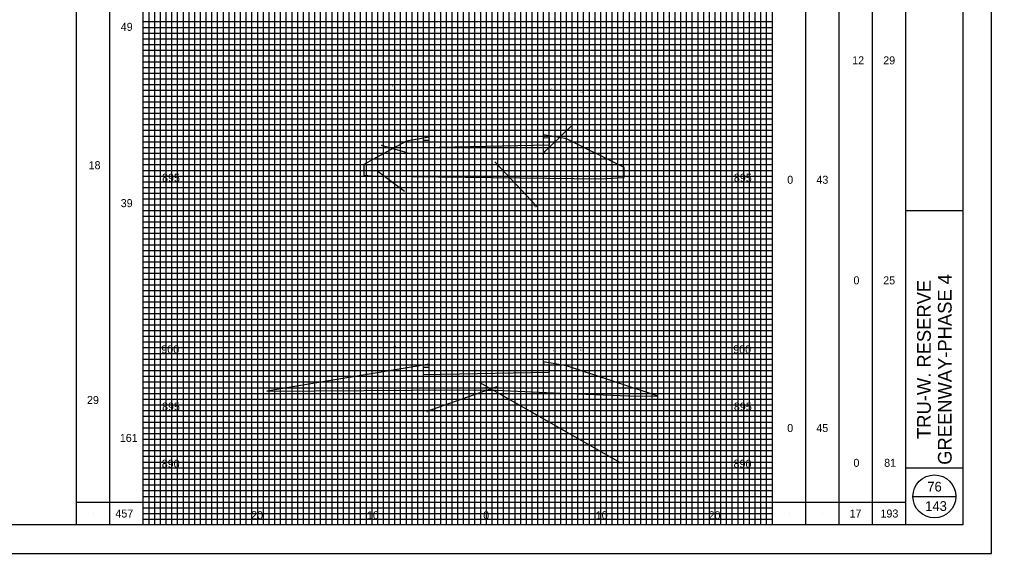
# Model space of a CAD drawing. Extents: x -73 to 160, y -2 to 1877.
# Drawn here: x 75 to 160, y 227.5 to 274.2 of the extents above; entities that cross this region are included whole.
import ezdxf

# ---------------------------------------------------------------- set-up
doc = ezdxf.new("R2010")
doc.units = 0
for name, color, linetype in [('DR_P_Flood_Boundary', 7, 'Continuous'), ('GK_Cells', 7, 'Continuous'), ('RD_X_Fence', 7, 'Continuous'), ('TX_X_5', 7, 'Continuous'), ('UT_P_Water_Cells', 7, 'Continuous'), ('XS_P_Pavt_Layers', 7, 'Continuous'), ('XS_P_Pavt_Surface', 7, 'Continuous'), ('XS_X_Ground_Line', 7, 'Continuous')]:
    doc.layers.add(name, color=color, linetype=linetype)

msp = doc.modelspace()

# ---------------------------------------------------------------- linework, layer by layer
at = {"layer": 'DR_P_Flood_Boundary'}
for p, q in [((90.832, 230), (90.832, 335)), ((95.832, 230), (95.832, 335)), ((100.832, 230), (100.832, 335)), ((105.832, 230), (105.832, 335)), ((110.832, 230), (110.832, 335)), ((115.832, 230), (115.832, 335)), ((120.832, 230), (120.832, 335)), ((125.832, 230), (125.832, 335)), ((130.832, 230), (130.832, 335)), ((135.832, 230), (135.832, 335)), ((85.832, 270), (140.832, 270)), ((85.832, 265), (140.832, 265)), ((85.832, 260), (140.832, 260)), ((85.832, 255), (140.832, 255)), ((85.832, 250), (140.832, 250)), ((85.832, 245), (140.832, 245)), ((85.832, 240), (140.832, 240)), ((85.832, 235), (140.832, 235))]:
    msp.add_line(p, q, dxfattribs=at)
at = {"layer": 'GK_Cells'}
for p, q in [((152.5, 230), (152.5, 335)), ((152.5, 257.5), (157.5, 257.5)), ((152.5, 235), (157.5, 235))]:
    msp.add_line(p, q, dxfattribs=at)
msp.add_lwpolyline([(0, 335), (157.5, 335), (157.5, 230), (0, 230)], close=True, dxfattribs=at)
at = {"layer": 'RD_X_Fence'}
for p, q in [((120.719, 262.403), (123.237, 264.87)), ((110.832, 263.9), (108.832, 263.567)), ((110.332, 263.64), (110.832, 263.65)), ((110.332, 262.973), (110.332, 263.64)), ((120.832, 263.85), (121.332, 263.86)), ((121.332, 263.86), (121.332, 263.193)), ((127.866, 261.25), (122.832, 263.767)), ((108.901, 262.546), (106.646, 263.188)), ((121.332, 263.193), (110.332, 262.973)), ((105.123, 261.511), (105.123, 260.571)), ((116.57, 261.744), (120.23, 257.835)), ((127.866, 260.374), (127.866, 261.25)), ((105.123, 260.571), (105.832, 260.51)), ((106.334, 260.939), (108.682, 259.172)), ((125.832, 260.25), (127.866, 260.374)), ((110.832, 244.05), (96.645, 241.685)), ((122.832, 243.917), (120.832, 244.25)), ((120.832, 244), (121.332, 244.01)), ((121.332, 244.01), (121.332, 243.343)), ((110.332, 243.79), (110.832, 243.8)), ((110.332, 243.123), (110.332, 243.79)), ((121.332, 243.343), (110.332, 243.123)), ((130.84, 241.247), (122.832, 243.917)), ((115.258, 242.457), (127.523, 235.468)), ((96.645, 241.685), (109.332, 241.79)), ((109.332, 241.79), (112.308, 241.814)), ((116.749, 242.071), (110.613, 239.914)), ((112.308, 241.814), (115.833, 241.782)), ((116.697, 241.774), (120.445, 241.609)), ((120.445, 241.609), (122.332, 241.53))]:
    msp.add_line(p, q, dxfattribs=at)
for points in [[(108.832, 263.567), (107.639, 262.905), (105.123, 261.511)], [(110.832, 263.65), (110.832, 263.796), (110.832, 263.9)], [(122.832, 263.767), (122.216, 263.869), (120.832, 264.1)], [(120.832, 264.1), (120.832, 263.996), (120.832, 263.85)], [(105.832, 260.51), (106.923, 260.496), (125.832, 260.25)], [(110.832, 243.8), (110.832, 243.946), (110.832, 244.05)], [(120.832, 244.25), (120.832, 244.146), (120.832, 244)], [(115.833, 241.782), (115.924, 241.781), (116.697, 241.774)], [(122.332, 241.53), (128.241, 241.281), (130.84, 241.247)]]:
    msp.add_lwpolyline(points, dxfattribs=at)
at = {"layer": 'TX_X_5'}
msp.add_lwpolyline([(-10, 227.5), (160, 227.5), (160, 337.5), (-10, 337.5)], close=True, dxfattribs=at)
at = {"layer": 'UT_P_Water_Cells'}
for p, q in [((86.332, 230), (86.332, 335)), ((86.832, 230), (86.832, 335)), ((87.332, 230), (87.332, 335)), ((87.832, 230), (87.832, 335)), ((88.332, 230), (88.332, 335)), ((88.832, 230), (88.832, 335)), ((89.332, 230), (89.332, 335)), ((89.832, 230), (89.832, 335)), ((90.332, 230), (90.332, 335)), ((91.332, 230), (91.332, 335)), ((91.832, 230), (91.832, 335)), ((92.332, 230), (92.332, 335)), ((92.832, 230), (92.832, 335)), ((93.332, 230), (93.332, 335)), ((93.832, 230), (93.832, 335)), ((94.332, 230), (94.332, 335)), ((94.832, 230), (94.832, 335)), ((95.332, 230), (95.332, 335)), ((96.332, 230), (96.332, 335)), ((96.832, 230), (96.832, 335)), ((97.332, 230), (97.332, 335)), ((97.832, 230), (97.832, 335)), ((98.332, 230), (98.332, 335)), ((98.832, 230), (98.832, 335)), ((99.332, 230), (99.332, 335)), ((99.832, 230), (99.832, 335)), ((100.332, 230), (100.332, 335)), ((101.332, 230), (101.332, 335)), ((101.832, 230), (101.832, 335)), ((102.332, 230), (102.332, 335)), ((102.832, 230), (102.832, 335)), ((103.332, 230), (103.332, 335)), ((103.832, 230), (103.832, 335)), ((104.332, 230), (104.332, 335)), ((104.832, 230), (104.832, 335)), ((105.332, 230), (105.332, 335)), ((106.332, 230), (106.332, 335)), ((106.832, 230), (106.832, 335)), ((107.332, 230), (107.332, 335)), ((107.832, 230), (107.832, 335)), ((108.332, 230), (108.332, 335)), ((108.832, 230), (108.832, 335)), ((109.332, 230), (109.332, 335)), ((109.832, 230), (109.832, 335)), ((110.332, 230), (110.332, 335)), ((111.332, 230), (111.332, 335)), ((111.832, 230), (111.832, 335)), ((112.332, 230), (112.332, 335)), ((112.832, 230), (112.832, 335)), ((113.332, 230), (113.332, 335)), ((113.832, 230), (113.832, 335)), ((114.332, 230), (114.332, 335)), ((114.832, 230), (114.832, 335)), ((115.332, 230), (115.332, 335)), ((116.332, 230), (116.332, 335)), ((116.832, 230), (116.832, 335)), ((117.332, 230), (117.332, 335)), ((117.832, 230), (117.832, 335)), ((118.332, 230), (118.332, 335)), ((118.832, 230), (118.832, 335)), ((119.332, 230), (119.332, 335)), ((119.832, 230), (119.832, 335)), ((120.332, 230), (120.332, 335)), ((121.332, 230), (121.332, 335)), ((121.832, 230), (121.832, 335)), ((122.332, 230), (122.332, 335)), ((122.832, 230), (122.832, 335)), ((123.332, 230), (123.332, 335)), ((123.832, 230), (123.832, 335)), ((124.332, 230), (124.332, 335)), ((124.832, 230), (124.832, 335)), ((125.332, 230), (125.332, 335)), ((126.332, 230), (126.332, 335)), ((126.832, 230), (126.832, 335)), ((127.332, 230), (127.332, 335)), ((127.832, 230), (127.832, 335)), ((128.332, 230), (128.332, 335)), ((128.832, 230), (128.832, 335)), ((129.332, 230), (129.332, 335)), ((129.832, 230), (129.832, 335)), ((130.332, 230), (130.332, 335)), ((131.332, 230), (131.332, 335)), ((131.832, 230), (131.832, 335)), ((132.332, 230), (132.332, 335)), ((132.832, 230), (132.832, 335)), ((133.332, 230), (133.332, 335)), ((133.832, 230), (133.832, 335)), ((134.332, 230), (134.332, 335)), ((134.832, 230), (134.832, 335)), ((135.332, 230), (135.332, 335)), ((136.332, 230), (136.332, 335)), ((136.832, 230), (136.832, 335)), ((137.332, 230), (137.332, 335)), ((137.832, 230), (137.832, 335)), ((138.332, 230), (138.332, 335)), ((138.832, 230), (138.832, 335)), ((139.332, 230), (139.332, 335)), ((139.832, 230), (139.832, 335)), ((140.332, 230), (140.332, 335)), ((85.832, 274), (140.832, 274)), ((85.832, 273.5), (140.832, 273.5)), ((85.832, 273), (140.832, 273)), ((85.832, 272.5), (140.832, 272.5)), ((85.832, 272), (140.832, 272)), ((85.832, 271.5), (140.832, 271.5)), ((85.832, 271), (140.832, 271)), ((85.832, 270.5), (140.832, 270.5)), ((85.832, 269.5), (140.832, 269.5)), ((85.832, 269), (140.832, 269)), ((85.832, 268.5), (140.832, 268.5)), ((85.832, 268), (140.832, 268)), ((85.832, 267.5), (140.832, 267.5)), ((85.832, 267), (140.832, 267)), ((85.832, 266.5), (140.832, 266.5)), ((85.832, 266), (140.832, 266)), ((85.832, 265.5), (140.832, 265.5)), ((85.832, 264.5), (140.832, 264.5)), ((85.832, 264), (140.832, 264)), ((85.832, 263.5), (140.832, 263.5)), ((85.832, 263), (140.832, 263)), ((85.832, 262.5), (140.832, 262.5)), ((85.832, 262), (140.832, 262)), ((85.832, 261.5), (140.832, 261.5)), ((85.832, 261), (140.832, 261)), ((85.832, 260.5), (140.832, 260.5)), ((85.832, 259.5), (140.832, 259.5)), ((85.832, 259), (140.832, 259)), ((85.832, 258.5), (140.832, 258.5)), ((85.832, 258), (140.832, 258)), ((85.832, 257.5), (140.832, 257.5)), ((85.832, 257), (140.832, 257)), ((85.832, 256.5), (140.832, 256.5)), ((85.832, 256), (140.832, 256)), ((85.832, 255.5), (140.832, 255.5)), ((85.832, 254.5), (140.832, 254.5)), ((85.832, 254), (140.832, 254)), ((85.832, 253.5), (140.832, 253.5)), ((85.832, 253), (140.832, 253)), ((85.832, 252.5), (140.832, 252.5)), ((85.832, 252), (140.832, 252)), ((85.832, 251.5), (140.832, 251.5)), ((85.832, 251), (140.832, 251)), ((85.832, 250.5), (140.832, 250.5)), ((85.832, 249.5), (140.832, 249.5)), ((85.832, 249), (140.832, 249)), ((85.832, 248.5), (140.832, 248.5)), ((85.832, 248), (140.832, 248)), ((85.832, 247.5), (140.832, 247.5)), ((85.832, 247), (140.832, 247)), ((85.832, 246.5), (140.832, 246.5)), ((85.832, 246), (140.832, 246)), ((85.832, 245.5), (140.832, 245.5)), ((85.832, 244.5), (140.832, 244.5)), ((85.832, 244), (140.832, 244)), ((85.832, 243.5), (140.832, 243.5)), ((85.832, 243), (140.832, 243)), ((85.832, 242.5), (140.832, 242.5)), ((85.832, 242), (140.832, 242)), ((85.832, 241.5), (140.832, 241.5)), ((85.832, 241), (140.832, 241)), ((85.832, 240.5), (140.832, 240.5)), ((85.832, 239.5), (140.832, 239.5)), ((85.832, 239), (140.832, 239)), ((85.832, 238.5), (140.832, 238.5)), ((85.832, 238), (140.832, 238)), ((85.832, 237.5), (140.832, 237.5)), ((85.832, 237), (140.832, 237)), ((85.832, 236.5), (140.832, 236.5)), ((85.832, 236), (140.832, 236)), ((85.832, 235.5), (140.832, 235.5)), ((85.832, 234.5), (140.832, 234.5)), ((85.832, 234), (140.832, 234)), ((85.832, 233.5), (140.832, 233.5)), ((85.832, 233), (140.832, 233)), ((85.832, 232.5), (140.832, 232.5)), ((85.832, 232), (140.832, 232)), ((85.832, 231.5), (140.832, 231.5)), ((85.832, 231), (140.832, 231)), ((85.832, 230.5), (140.832, 230.5))]:
    msp.add_line(p, q, dxfattribs=at)
at = {"layer": 'XS_X_Ground_Line'}
for p, q in [((80, 230), (80, 335)), ((85.832, 230), (85.832, 335)), ((140.832, 230), (140.832, 335)), ((146.667, 230), (146.667, 335)), ((82.916, 230), (82.916, 333.75)), ((143.75, 230), (143.75, 333.75)), ((149.583, 230), (149.583, 333.75)), ((155, 246.458), (155, 246.458)), ((155, 232.925), (155, 232.925)), ((153.125, 232.5), (156.875, 232.5)), ((80, 232), (85.832, 232)), ((140.832, 232), (152.5, 232)), ((155, 231.225), (155, 231.225)), ((81.458, 231.03), (81.458, 231.03)), ((84.374, 231.03), (84.374, 231.03)), ((142.291, 231), (142.291, 231)), ((145.209, 231), (145.209, 231)), ((148.125, 231), (148.125, 231)), ((151.042, 231), (151.042, 231))]:
    msp.add_line(p, q, dxfattribs=at)
msp.add_circle((155, 232.5), 1.875, dxfattribs=at)

# ---------------------------------------------------------------- texts
at = {"layer": 'RD_X_Fence'}
for s, p in [('3.1', (107.527, 268.309)), ('2.0', (109.247, 268.388)), ('2.0', (121.285, 267.994)), ('3.2', (123.982, 267.836)), ('5.6', (123.087, 264.8)), ('2.2', (106.502, 263.118)), ('58.9', (120.01, 257.765)), ('7.9', (107.665, 245.542)), ('2.0', (121.641, 245.169)), ('5.0', (123.997, 245.2)), ('15.1', (110.46, 239.844)), ('45.0', (127.301, 235.398))]:
    msp.add_text(s, height=0.14, dxfattribs=at).set_placement(p)
at = {"layer": 'XS_P_Pavt_Layers'}
for s, p in [('76', (154.381, 232.925)), ('143', (154.197, 231.225))]:
    msp.add_text(s, height=0.85, dxfattribs=at).set_placement(p)
at = {"layer": 'XS_P_Pavt_Surface'}
for s, p in [('49', (83.858, 273.198)), ('12', (147.812, 270.267)), ('29', (150.529, 270.267)), ('18', (81.048, 261.102)), ('895', (87.471, 260)), ('895', (137.471, 260)), ('0', (142.133, 259.829)), ('43', (144.684, 259.829)), ('39', (83.856, 257.785)), ('0', (147.925, 251.035)), ('25', (150.526, 251.035)), ('900', (87.41, 245)), ('900', (137.41, 245)), ('29', (80.907, 240.574)), ('895', (87.471, 240)), ('895', (137.471, 240)), ('0', (142.133, 238.126)), ('45', (144.678, 238.126)), ('161', (83.776, 237.257)), ('890', (87.443, 235)), ('890', (137.443, 235)), ('0', (147.925, 235.082)), ('81', (150.609, 235.082)), ('457', (83.388, 230.65)), ('20', (95.257, 230.5)), ('10', (105.389, 230.5)), ('0', (115.554, 230.5)), ('0', (115.554, 230.5)), ('10', (125.389, 230.5)), ('20', (135.257, 230.5)), ('17', (147.582, 230.65)), ('193', (150.287, 230.65))]:
    msp.add_text(s, height=0.7, dxfattribs=at).set_placement(p)
for s, p in [('GREENWAY-PHASE 4', (156.512, 235.261)), ('TRU-W. RESERVE', (154.688, 237.519))]:
    msp.add_text(s, height=1.2, rotation=90, dxfattribs=at).set_placement(p)
at = {"layer": 'XS_X_Ground_Line'}
msp.add_text('143', height=0.85, dxfattribs=at).set_placement((154.197, 231.225))

doc.saveas('drawing.dxf')
